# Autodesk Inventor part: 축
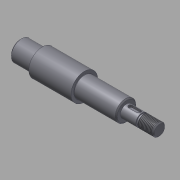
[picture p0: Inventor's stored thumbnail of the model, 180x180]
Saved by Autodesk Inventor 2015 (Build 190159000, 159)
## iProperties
Created: 2015-12
Part Number: 축
Material: 강철, 연강
Document SubType Name: Modeling
Designer: mdu
Density: 7.86 g/cm^3
Appearance: 강철
CustomPartVersion: 1
Author: mdu
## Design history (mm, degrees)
sketch "스케치5"
  geometry: L1 (0, 0)-(135, 0); L2 (0, 0)-(135, 0); L3 (135, 0)-(135, 6); L4 (103, 6)-(103, 10); L5 (103, 10)-(62, 10); L6 (62, 10)-(62, 13); L7 (62, 13)-(21, 13); L8 (21, 13)-(21, 10); L9 (21, 10)-(0, 10); L10 (0, 10)-(0, 0); L11 (118, 6)-(118, 5); L12 (118, 5)-(120, 5); L13 (120, 5)-(120, 6); L14 (135, 6)-(120, 6); L15 (118, 6)-(103, 6)
  constraints: 31 end point, 12 perpendicular, 9 parallel, 1 collinear, 1 horizontal
  dimensions: "d43" = 20 diameter of L9 L1; "d44" = 26 diameter of L7 L1; "d45" = 20 diameter of L5 L2; "d47" = 41 distance of L6.end L7.end; "d48" = 32 distance between parallel lines of L3 L4; "d50" = 21 distance of L8.end L9.end; "d52" = 12 diameter of L14 L1; "d53" = 15 distance between parallel lines of L3 L13; "d54" = 2 distance of L11.end L12.end; "d55" = 1 distance between parallel lines of L14 L12; "d64" = 135 distance of L1.start L1.end
revolve "회전4" sketch "스케치5" stored, may be unused: angle "d51" = 90 deg
feature "스레드6" dims "d56" = 10, "d57" = 0
chamfer "모따기6" distance "d32" = 1; stored, may be unused: second distance "d33" = 0.4, angle "d34" = 45 deg
chamfer "모따기5" distance "d27" = 1; stored, may be unused: second distance "d28" = 0.125, angle "d29" = 45 deg
fillet "모깎기1" dims "d17" = 0.3
fillet "모깎기2" dims "d18" = 0.3
chamfer "모따기3" distance "d19" = 1; stored, may be unused: second distance "d20" = 1, angle "d21" = 45 deg
node "작업 평면1"
sketch "스케치6"
  geometry: L1 (-3.5, 2)-(4.5, 2); L2 (4.5, -2)-(-3.5, -2); L3 (-7.5, 9)-(-7.5, -9) reference; A1 r 2 centre (4.5, 0) between (4.5, -2) and (4.5, 2); A2 r 2 centre (-3.5, 0) between (-3.5, 2) and (-3.5, -2); 1 further point
  constraints: 4 end point, 4 point on circle, 4 tangent, 2 centre point, 1 horizontal, 1 horizontal alignment, 1 parallel
  dimensions: "d59" = 2 distance edge to line of A2 L3; "d60" = 12 dimension on A1 A2; "d61" = 4 distance between parallel lines of L2 L1
extrude "돌출1" cut sketch "스케치6" distance "d62" = 2.3; taper "d63" = 0 deg
node "솔리드1"
node "솔리드2"
other parameters: "d46" = 12
